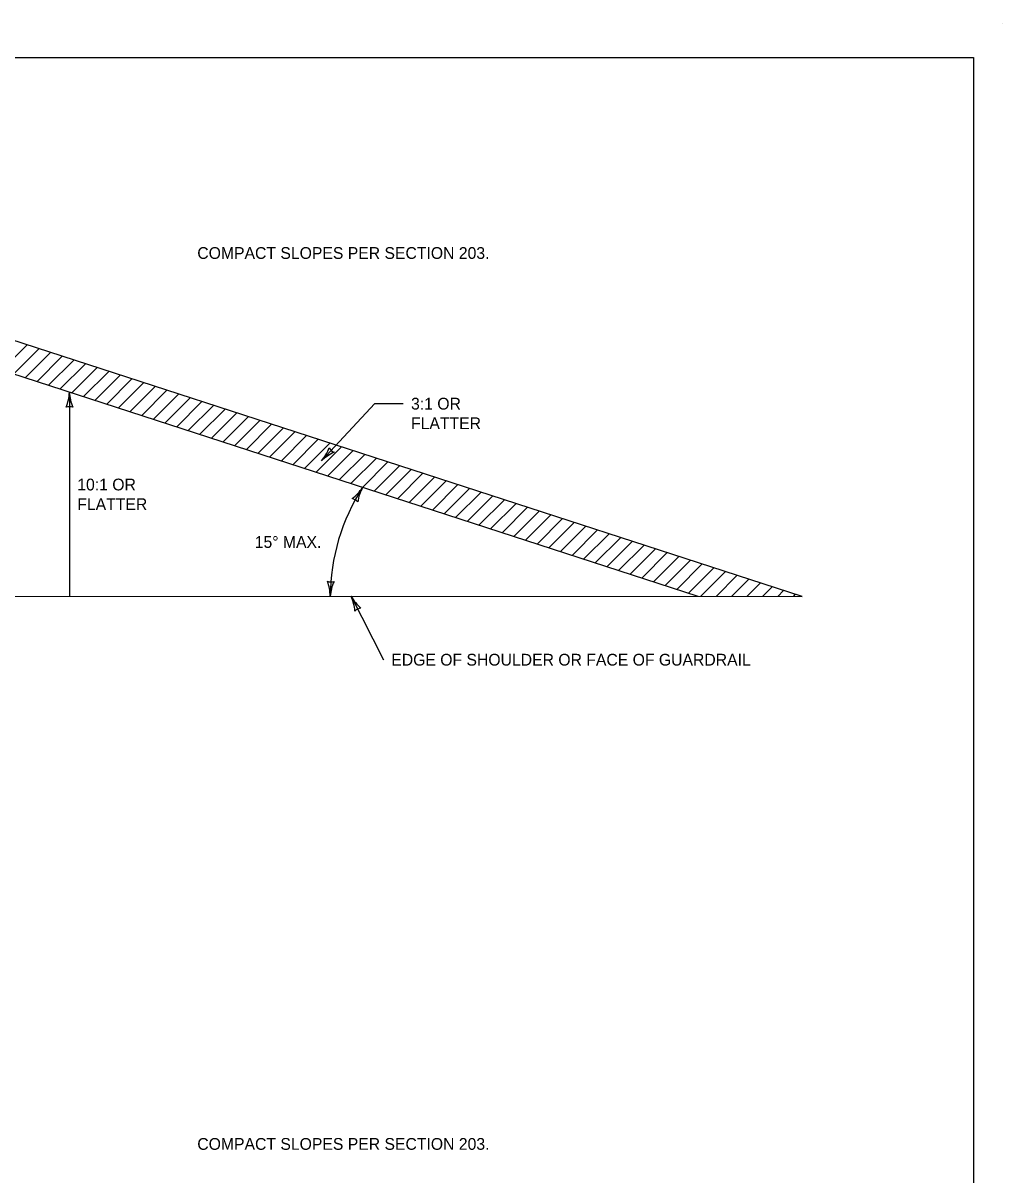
# Model space of a CAD drawing. Extents: x 49991.4 to 50021, y 49987.6 to 50011.4.
# Drawn here: x 50011.91 to 50016.9, y 49993.3 to 49999.18 of the extents above; entities that cross this region are included whole.
import ezdxf

# ---------------------------------------------------------------- set-up
doc = ezdxf.new("R2010")
doc.units = 0
for name, color, linetype in [('Level 1', 7, 'Continuous'), ('Level 2', 7, 'Continuous'), ('Level 3', 7, 'Continuous')]:
    doc.layers.add(name, color=color, linetype=linetype)

msp = doc.modelspace()

# ---------------------------------------------------------------- linework, layer by layer
at = {"layer": 'Level 1'}
for p, q in [((50016.9001, 49999.1756), (50016.9001, 49999.1756)), ((50015.8765, 49996.2537), (50011.0311, 49997.8254)), ((50015.3468, 49996.2537), (50011.0311, 49997.6537)), ((50011.9264, 49997.535), (50011.7967, 49997.4053)), ((50011.9857, 49997.5158), (50011.856, 49997.386)), ((50012.045, 49997.4965), (50011.9153, 49997.3668)), ((50012.1044, 49997.4772), (50011.9747, 49997.3476)), ((50012.1637, 49997.458), (50012.034, 49997.3283)), ((50012.223, 49997.4388), (50012.0933, 49997.3091)), ((50012.2823, 49997.4195), (50012.1526, 49997.2898)), ((50012.3416, 49997.4003), (50012.212, 49997.2706)), ((50012.4009, 49997.381), (50012.2713, 49997.2513)), ((50012.4603, 49997.3618), (50012.3306, 49997.2321)), ((50012.5197, 49997.3425), (50012.3899, 49997.2129)), ((50012.5789, 49997.3233), (50012.4493, 49997.1936)), ((50012.6382, 49997.3041), (50012.5085, 49997.1744)), ((50012.6976, 49997.2848), (50012.5679, 49997.1551)), ((50012.7569, 49997.2656), (50012.6273, 49997.1359)), ((50012.8162, 49997.2463), (50012.6865, 49997.1166)), ((50012.8756, 49997.2271), (50012.7458, 49997.0974)), ((50012.9348, 49997.2079), (50012.8052, 49997.0782)), ((50012.9942, 49997.1886), (50012.8645, 49997.0589)), ((50013.0535, 49997.1694), (50012.9238, 49997.0397)), ((50013.1129, 49997.1501), (50012.9832, 49997.0204)), ((50013.1722, 49997.1309), (50013.0425, 49997.0012)), ((50013.2315, 49997.1116), (50013.1018, 49996.9819)), ((50013.2908, 49997.0924), (50013.1611, 49996.9627)), ((50013.3501, 49997.0732), (50013.2205, 49996.9434)), ((50013.4095, 49997.0539), (50013.2798, 49996.9242)), ((50013.4688, 49997.0346), (50013.3391, 49996.905)), ((50013.5281, 49997.0154), (50013.3985, 49996.8857)), ((50013.5875, 49996.9962), (50013.4577, 49996.8665)), ((50013.6467, 49996.9769), (50013.517, 49996.8472)), ((50013.706, 49996.9577), (50013.5764, 49996.828)), ((50013.7654, 49996.9384), (50013.6357, 49996.8087)), ((50013.8247, 49996.9192), (50013.695, 49996.7895)), ((50013.8841, 49996.8999), (50013.7543, 49996.7703)), ((50013.9434, 49996.8807), (50013.8137, 49996.751)), ((50014.0027, 49996.8615), (50013.873, 49996.7318)), ((50014.062, 49996.8422), (50013.9323, 49996.7125)), ((50014.1213, 49996.823), (50013.9916, 49996.6933)), ((50014.1807, 49996.8037), (50014.051, 49996.674)), ((50014.24, 49996.7845), (50014.1103, 49996.6548)), ((50014.2993, 49996.7652), (50014.1696, 49996.6356)), ((50014.3586, 49996.746), (50014.2289, 49996.6163)), ((50014.418, 49996.7267), (50014.2883, 49996.597)), ((50014.4773, 49996.7075), (50014.3476, 49996.5778)), ((50014.5366, 49996.6883), (50014.4069, 49996.5586)), ((50014.5959, 49996.669), (50014.4662, 49996.5393)), ((50014.6552, 49996.6498), (50014.5255, 49996.5201)), ((50014.7146, 49996.6305), (50014.5849, 49996.5008)), ((50014.7739, 49996.6113), (50014.6442, 49996.4816)), ((50014.8332, 49996.5921), (50014.7035, 49996.4624)), ((50014.8925, 49996.5728), (50014.7628, 49996.4431)), ((50014.9519, 49996.5536), (50014.8222, 49996.4239)), ((50015.0112, 49996.5343), (50014.8815, 49996.4046)), ((50015.0705, 49996.5151), (50014.9408, 49996.3854)), ((50015.1298, 49996.4958), (50015.0001, 49996.3661)), ((50015.1892, 49996.4766), (50015.0595, 49996.3469)), ((50015.2485, 49996.4574), (50015.1188, 49996.3277)), ((50015.3078, 49996.4381), (50015.1781, 49996.3084)), ((50015.3671, 49996.4189), (50015.2374, 49996.2892)), ((50015.4265, 49996.3997), (50015.2967, 49996.2699)), ((50015.4265, 49996.3996), (50015.2968, 49996.2699)), ((50015.4858, 49996.3805), (50015.359, 49996.2537)), ((50015.5451, 49996.3613), (50015.4375, 49996.2537)), ((50015.6044, 49996.342), (50015.5161, 49996.2537)), ((50015.6638, 49996.3228), (50015.5947, 49996.2537)), ((50015.6636, 49996.3222), (50015.5951, 49996.2537)), ((50000.2381, 49996.2551), (50015.8765, 49996.2537)), ((50015.7229, 49996.3029), (50015.6736, 49996.2537)), ((50015.7822, 49996.2837), (50015.7521, 49996.2537)), ((50015.8415, 49996.2645), (50015.8307, 49996.2537))]:
    msp.add_line(p, q, dxfattribs=at)
msp.add_lwpolyline([(49999.3835, 49998.9992), (50016.7501, 49998.9992), (50016.7501, 49987.7988), (49999.3835, 49987.7988)], close=True, dxfattribs=at)
at = {"layer": 'Level 3'}
for p, q in [((50012.1416, 49997.2934), (50012.1416, 49996.254)), ((50013.426, 49996.9438), (50013.6985, 49997.2358)), ((50013.6985, 49997.2358), (50013.8429, 49997.2358)), ((50013.5772, 49996.2539), (50013.7421, 49995.9307))]:
    msp.add_line(p, q, dxfattribs=at)
for centre, radius, start, end in [((50011.9089, 49997.3049), 0.233, 337.92284, 357.17269), ((50012.3637, 49997.3025), 0.2223, 182.36048, 202.54399), ((50012.1416, 49997.1652), 0.0548, 72.13882, 107.86118), ((50013.2574, 49997.0886), 0.2223, 319.33891, 339.52242), ((50013.5135, 49997.0375), 0.0548, 209.11725, 244.83961), ((50013.5883, 49996.7766), 0.233, 114.90127, 134.15112), ((50014.506, 49996.2481), 1.0352, 147.20901, 179.67838), ((50013.4502, 49996.9312), 0.2223, 306.40221, 326.58572), ((50013.841, 49996.6985), 0.233, 151.77351, 171.02336), ((50013.5696, 49996.6989), 0.0548, 41.08502, 76.80738), ((50013.4753, 49996.382), 0.0548, 250.10224, 285.8246), ((50013.2378, 49996.2507), 0.233, 0.79073, 20.04058), ((50013.6925, 49996.2369), 0.2223, 155.41943, 175.60294), ((50013.3752, 49996.1611), 0.2223, 4.48723, 24.67074), ((50013.7793, 49996.3699), 0.233, 209.85853, 229.10838), ((50013.6355, 49996.1397), 0.0548, 99.17004, 134.8924)]:
    msp.add_arc(centre, radius, start, end, dxfattribs=at)

# ---------------------------------------------------------------- texts
at = {"layer": 'Level 2'}
for s, p in [('COMPACT SLOPES PER SECTION 203.', (50012.7934, 49997.9735)), ('3:1 OR', (50013.8829, 49997.2056)), ('FLATTER', (50013.8829, 49997.1057)), ('10:1 OR', (50012.1816, 49996.7935)), ('FLATTER', (50012.1816, 49996.6935)), ('15° MAX.', (50013.0862, 49996.5006)), ('EDGE OF SHOULDER OR FACE OF GUARDRAIL', (50013.7821, 49995.9007)), ('COMPACT SLOPES PER SECTION 203.', (50012.7934, 49993.4328))]:
    msp.add_text(s, height=0.06, dxfattribs=at).set_placement(p)

doc.saveas('drawing.dxf')
